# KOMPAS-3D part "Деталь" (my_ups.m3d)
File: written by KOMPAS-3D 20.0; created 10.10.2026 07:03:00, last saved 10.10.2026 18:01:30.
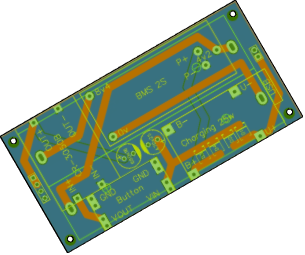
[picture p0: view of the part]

Document properties: Полное имя файла: D:\myProjects\Progect_esp32\box_compas\my_ups.m3d

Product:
- Part/product: Деталь
    Масса: 0.0459981

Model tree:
1. Эскиз:1
2. Элемент выдавливания:1
     Расстояние 1 = 1.5
3. Эскиз:2  (with: Элемент выдавливания:1)
4. Элемент выдавливания:2
     Расстояние 2 = 1.5
5. Массив по сетке:1  (with: Элемент выдавливания:2, Эскиз:2)  (4 pattern instances)
     Шаг 1 = 83; Угол раствора = -90; Шаг 2 = 37

Referenced files in D:\myProjects\Progect_esp32\box_compas\: my_ups.png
